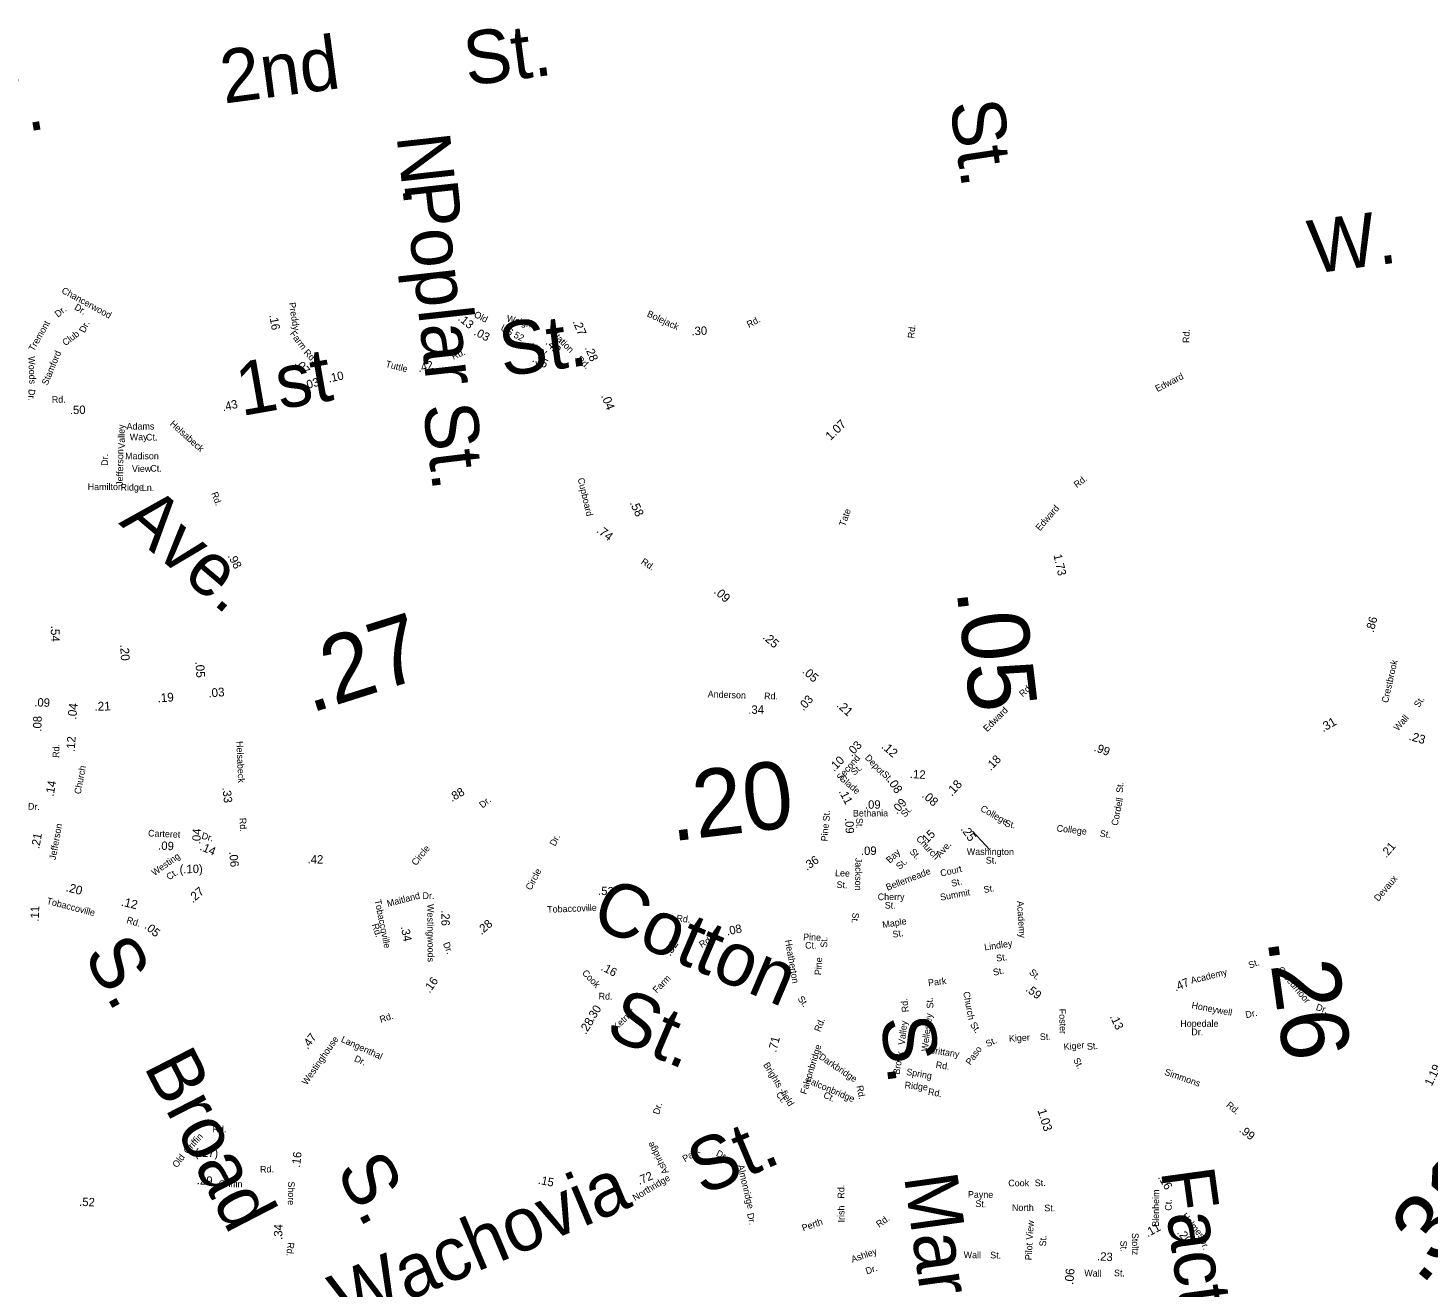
# Model space of a CAD drawing. Extents: x 1553981 to 1780076, y 812965 to 996873.
# Drawn here: x 1630177 to 1632669, y 853916 to 856157 of the extents above; entities that cross this region are included whole.
import ezdxf

# ---------------------------------------------------------------- set-up
doc = ezdxf.new("R2010")
doc.units = 0
for name, color, linetype in [('Exist Road Non-System Type 51 Label', 7, 'Continuous'), ('Exist Road Primary NC Service Mileage Hundredths English Label', 7, 'Continuous'), ('Exist Road Secondary Mileage Hundredths English Label', 7, 'Continuous'), ('Map Preparation Border Antique Large Shape', 7, 'Continuous')]:
    doc.layers.add(name, color=color, linetype=linetype)

msp = doc.modelspace()

# ---------------------------------------------------------------- linework, layer by layer
at = {"layer": 'Exist Road Non-System Type 51 Label'}
msp.add_lwpolyline([(1631858.1, 854727.1), (1631889.3, 854693.9)], dxfattribs=at)

# ---------------------------------------------------------------- texts
for s, height, rotation, p in [('St.', 95, 7.4271, (1630958.8, 856054.2)), ('2nd', 95, 7.5891, (1630525.6, 856022.5)), ('W.', 95, 9.3723, (1630057.1, 855953.2)), ('St.', 95, 278.5556, (1631817.1, 856023.5)), ('N.', 95, 276.3247, (1630832.7, 855965.2)), ('Poplar', 95, 276.3247, (1630846.1, 855881.1)), ('W.', 95, 7.5901, (1632463, 855719.5)), ('Chancerwood', 11.875, 331.4592, (1630235.2, 855686.3)), ('Dr.', 11.88, 37.7398, (1630229.8, 855641.4)), ('Dr.', 11.88, 329.0091, (1630258, 855657.1)), ('Tremont', 11.88, 60.167, (1630187, 855580.6)), ('Dr.', 11.88, 63.6142, (1630277.5, 855613.5)), ('St.', 95, 7.605, (1631022.1, 855536.9)), ('Club', 11.87, 36.9084, (1630243.1, 855590.6)), ('Stamford', 11.88, 67.2967, (1630211.3, 855520.2)), ('1st', 95, 9.919, (1630556.2, 855466.1)), ('Woods', 11.88, 272.3922, (1630177.1, 855572.5)), ('Dr.', 11.88, 268.7345, (1630177.6, 855514.5)), ('St.', 95, 276.9276, (1630879.4, 855485)), ('Valley', 11.88, 91.1337, (1630349.3, 855408.3)), ('Jefferson', 11.88, 89.3274, (1630345.8, 855341.9)), ('Dr.', 11.88, 90, (1630319.1, 855377.7)), ('Madison', 11.87, 359.9238, (1630349.5, 855389.4)), ('View', 11.87, 0.3117, (1630361.7, 855366.7)), ('Ct.', 11.88, 359.3313, (1630394.4, 855367.4)), ('Ave.', 95, 319.6591, (1630336.8, 855275.1)), ('St.', 11.88, 56.7224, (1632653, 854946.3)), ('Wall', 11.88, 49.0847, (1632615.6, 854904.9)), ('Depot', 11.87, 313.0043, (1631665.8, 854857.2)), ('St.', 11.88, 314.4276, (1631695.8, 854827.6)), ('St.', 11.88, 86.7449, (1632125.9, 854795.2)), ('Cordell', 11.87, 78.9341, (1632116.7, 854736.3)), ('St.', 11.88, 88.704, (1631603.8, 854744.7)), ('College', 11.87, 330.4152, (1631871.1, 854764.1)), ('Pine', 11.87, 86.1804, (1631600.3, 854708.8)), ('St.', 11.88, 347.1512, (1631914.6, 854736.2)), ('College', 11.88, 353.4808, (1632007.5, 854726.9)), ('Church', 11.88, 313.1543, (1631756.9, 854713)), ('St.', 11.88, 352.2827, (1632084.2, 854717.7)), ('Bay', 11.88, 44.7999, (1631711.2, 854669.2)), ('St.', 11.88, 313.1543, (1631745.4, 854689.8)), ('Ave.', 11.88, 48.2454, (1631800.4, 854679.5)), ('Washington', 11.88, 359.7339, (1631848, 854685.1)), ('St.', 11.88, 0.2268, (1631881.8, 854669.6)), ('Lee', 11.87, 357.9044, (1631613.3, 854647.2)), ('Jackson', 11.88, 269.2198, (1631649.7, 854679.9)), ('Bellemeade', 11.88, 21.3693, (1631706.7, 854621.1)), ('St.', 11.88, 44.7999, (1631728.9, 854658)), ('Court', 11.88, 12.6952, (1631802.2, 854646.4)), ('Cotton', 95, 336.8873, (1631175.3, 854560.6)), ('St.', 11.87, 357.9044, (1631616, 854626.3)), ('St.', 11.88, 12.6952, (1631821.7, 854628.2)), ('Maitland', 11.88, 14.7534, (1630817.4, 854592.3)), ('Dr.', 11.88, 359.8861, (1630879, 854606.6)), ('Cherry', 11.88, 0.4515, (1631689.5, 854604.4)), ('Summit', 11.88, 10.2169, (1631801.6, 854603.6)), ('St.', 11.87, 9.9072, (1631879.1, 854617.1)), ('St.', 11.88, 263.1054, (1631645, 854583)), ('St.', 11.87, 359.302, (1631701.9, 854589.5)), ('Maple', 11.87, 9.4837, (1631698.8, 854554.6)), ('S.', 95, 298.8589, (1630274.4, 854507.6)), ('Heatherton', 11.87, 279.9144, (1631524.3, 854532.9)), ('Pine', 11.88, 357.9687, (1631556.5, 854533.2)), ('St.', 11.88, 88.704, (1631599.4, 854519.8)), ('St.', 11.87, 9.4837, (1631716.7, 854537.5)), ('Lindley', 11.88, 8.0181, (1631879.9, 854515)), ('Ct.', 11.87, 0.0702, (1631560.2, 854518.1)), ('St.', 11.88, 8.0092, (1631901.2, 854495)), ('Pine', 11.87, 86.1804, (1631588.6, 854470.6)), ('St.', 11.88, 12.7917, (1631896.2, 854469.8)), ('Park', 11.88, 7.0393, (1631779.8, 854451.3)), ('St.', 95, 336.8873, (1631201.4, 854363.4)), ('St.', 11.88, 306.3077, (1631546.3, 854428.7)), ('Church', 11.88, 280.4137, (1631841.5, 854440.8)), ('Rd.', 11.88, 95.6977, (1631744.6, 854405.5)), ('St.', 11.88, 96.0298, (1631789, 854412.4)), ('Foster', 11.88, 272.1215, (1632012.1, 854411)), ('Honeywell', 11.87, 349.1792, (1632247.4, 854412)), ('Dr.', 11.88, 12.4372, (1632345.4, 854394.3)), ('Rd.', 11.87, 68.2472, (1631586.7, 854369)), ('S.', 95, 277.5158, (1631693.9, 854393.4)), ('Valley', 11.88, 83.413, (1631737.4, 854346.1)), ('Wellesley', 11.88, 83.1258, (1631778.5, 854334.7)), ('St.', 11.88, 303.7459, (1631853.3, 854382.6)), ('Hopedale', 11.88, 359.9933, (1632228.1, 854378.9)), ('Langenthal', 11.88, 335.4785, (1630732.9, 854352.7)), ('St.', 11.88, 25.0303, (1631885, 854342.5)), ('Kiger', 11.88, 3.2858, (1631923.4, 854352.2)), ('St.', 11.88, 2.2978, (1631978.3, 854355.2)), ('Dr.', 11.88, 0.3054, (1632247.8, 854363.8)), ('Broad', 95, 297.2142, (1630381.8, 854308.4)), ('Falconbridge', 11.875, 72.81, (1631562.4, 854257.7)), ('Darkbridge', 11.88, 326.0203, (1631583.5, 854323)), ('Brook', 11.88, 80.2186, (1631728.1, 854293.3)), ('Brittany', 11.88, 351.7451, (1631780.6, 854332)), ('Paso', 11.88, 54.5401, (1631854.6, 854309.8)), ('Kiger', 11.88, 6.1203, (1632021, 854337.2)), ('St.', 11.88, 6.1203, (1632062.5, 854337.7)), ('Dr.', 11.88, 335.4785, (1630756.3, 854318.2)), ('Brights -field', 11.875, 301.6463, (1631485.1, 854311.4)), ('Rd.', 11.88, 351.7451, (1631792.1, 854305.9)), ('St.', 11.88, 298.4184, (1632037, 854320)), ('Falconbridge', 11.875, 337.0718, (1631560.7, 854280.1)), ('Spring', 11.88, 350.2233, (1631739.6, 854293.4)), ('Ct.', 11.88, 306.2767, (1631507.5, 854258.4)), ('Ct.', 11.88, 334.7485, (1631591.5, 854253.6)), ('Rd.', 11.88, 281.3645, (1631651.4, 854273.4)), ('Ridge', 11.88, 353.8249, (1631736.9, 854269.8)), ('Rd.', 11.88, 350.0772, (1631778.3, 854258.1)), ('Dr.', 11.88, 74.2178, (1631300.2, 854221.9)), ('St.', 95, 22.8454, (1631377.3, 854078.1)), ('Ashridge', 11.88, 117.3404, (1631317.7, 854120.2)), ('S.', 95, 297.1298, (1630724.1, 854124.4)), ('Wachovia', 95, 22.8454, (1630741.4, 853843.8)), ('Almonridge', 11.88, 283.2611, (1631439.7, 854132.1)), ('Marshall', 95, 277.9213, (1631736.1, 854112.6)), ('Cook', 11.88, 0.5505, (1631921.9, 854094.8)), ('Factory', 95, 277.8122, (1632193.3, 854122.5)), ('Rd.', 11.88, 89.3522, (1631629.9, 854073.1)), ('Payne', 11.88, 359.5513, (1631850, 854074.6)), ('St.', 11.88, 1.0714, (1631969.1, 854095.1)), ('Irish', 11.87, 90.7296, (1631630.4, 854030.8)), ('St.', 11.88, 358.3709, (1631863.2, 854058.2)), ('North', 11.88, 359.8416, (1631928.4, 854051.2)), ('St.', 11.87, 359.3198, (1631986, 854050.6)), ('Dr.', 11.88, 283.2611, (1631456.6, 854046.1)), ('Perth', 11.87, 19.5353, (1631556.8, 854014.7)), ('Rd.', 11.88, 35.5755, (1631691.8, 854021.1)), ('View', 11.88, 85.9709, (1631965.3, 853999.5)), ('Ashley', 11.87, 18.9451, (1631644.4, 853959)), ('Pilot', 11.88, 87.0253, (1631963.5, 853963.1)), ('St.', 11.88, 87.0253, (1631989, 853987.8)), ('Wall', 11.88, 359.684, (1631842.4, 853967.1)), ('St.', 11.88, 358.9513, (1631889.6, 853966.7)), ('Dr.', 11.87, 18.9451, (1631670.1, 853937.9))]:
    msp.add_text(s, height=height, rotation=rotation, dxfattribs=at).set_placement(p)
for s, p in [('Adams', (1630352.1, 855442.3)), ('Way', (1630357.8, 855423.4)), ('Ct.', (1630386.8, 855422.8)), ('Hamilton', (1630282.9, 855334.5)), ('Ridge', (1630341.3, 855333.6)), ('Ln.', (1630379.3, 855333))]:
    msp.add_text(s, height=11.88, dxfattribs=at).set_placement(p)
at = {"layer": 'Exist Road Primary NC Service Mileage Hundredths English Label'}
for s, rotation, p in [('.27', 292.6199, (1631146, 855634.6)), ('.04', 291.7778, (1631196.8, 855502.4)), ('.58', 294.6468, (1631247.5, 855311.8)), ('.09', 318.8745, (1631396.7, 855152.1)), ('.25', 318.8745, (1631483.5, 855071)), ('.05', 318.8745, (1631553.8, 855010.1)), ('.21', 317.9085, (1631615.1, 854950)), ('.31', 29.8003, (1632482.5, 854903.3)), ('.12', 318.3274, (1631694.8, 854876.7)), ('.23', 343.8685, (1632634, 854890.1)), ('.08', 303.9069, (1631705.8, 854816.7)), ('.18', 47.2193, (1631821.2, 854788.6)), ('.08', 319.1979, (1631766.9, 854789.2)), ('.25', 305.1418, (1631836.4, 854731.2)), ('1.03', 287.3387, (1631973.8, 854230.3)), ('.06', 85.1469, (1632037.6, 853919.2))]:
    msp.add_text(s, height=15.62, rotation=rotation, dxfattribs=at).set_placement(p)
at = {"layer": 'Exist Road Secondary Mileage Hundredths English Label'}
for s, height, rotation, p in [('.16', 15, 279.9951, (1630606.1, 855645.9)), ('.13', 15, 320.8792, (1630941, 855638.1)), ('.03', 15, 332.7094, (1630969.1, 855611.5)), ('.30', 15, 2.7224, (1631358.2, 855610)), ('.42', 15, 315.3122, (1631096.9, 855595.7)), ('.28', 15, 292.536, (1631167.7, 855587.8)), ('.07', 15, 311.3959, (1630650.6, 855559.7)), ('.42', 15, 13.5336, (1630872.3, 855544.3)), ('.35', 15, 332.417, (1631073.1, 855563.9)), ('.03', 15, 15.3191, (1630669.4, 855513.2)), ('.10', 15, 12.2641, (1630712.5, 855526)), ('.50', 15, 0.9537, (1630251.3, 855469.7)), ('.43', 15, 13.2965, (1630524.1, 855474.9)), ('1.07', 15.62, 44.3494, (1631605.5, 855422)), ('.74', 15.62, 322.9183, (1631187.5, 855260.5)), ('.98', 15, 298.0586, (1630531.7, 855217.2)), ('1.73', 15, 282.7937, (1632002.3, 855218.9)), ('.05', 120, 276.7369, (1631829.5, 855156.3)), ('.27', 120, 17.5375, (1630678.9, 854937)), ('.86', 15, 74.96, (1632572.1, 855080.1)), ('.54', 15.62, 270.1556, (1630217.3, 855093.2)), ('.20', 15.62, 273.4682, (1630340.6, 855059.3)), ('.05', 15.62, 273.7213, (1630474.6, 855029)), ('.03', 15.62, 4.7201, (1630498.2, 854965.3)), ('.09', 15, 358.0897, (1630187.6, 854949.5)), ('.21', 15.62, 1.1233, (1630295, 854941.7)), ('.19', 15.62, 4.1596, (1630407.7, 854956.4)), ('.03', 15, 48.1457, (1631557.1, 854940.5)), ('.08', 15, 88.4934, (1630200.4, 854904.4)), ('.04', 15.62, 83.1993, (1630262.1, 854925.4)), ('.12', 15, 86.5245, (1630259.8, 854868)), ('.03', 15, 46.1907, (1631643.1, 854859.3)), ('.99', 15, 340.0908, (1632073.3, 854870.4)), ('.10', 15, 46.1494, (1631611.9, 854832.2)), ('.18', 15, 45.38, (1631890.6, 854834.1)), ('.20', 120, 6.9016, (1631323, 854709)), ('.12', 15, 356.5999, (1631746.4, 854821.9)), ('.14', 15, 79.5389, (1630222, 854788.3)), ('.33', 15, 276.4376, (1630522.6, 854804.6)), ('.88', 15, 29.9847, (1630931.3, 854779.1)), ('.11', 15, 297.6042, (1631619.6, 854798.1)), ('.09', 15, 0.1597, (1631666.7, 854767.2)), ('.09', 15, 48.3512, (1631723.7, 854756.6)), ('.04', 15, 86.9838, (1630483.5, 854703.7)), ('.09', 15, 272.5317, (1631631.3, 854750.5)), ('.21', 15, 79.6773, (1630196.6, 854695.1)), ('.09', 15, 357.4069, (1630408.1, 854694.4)), ('.15', 15, 45.7586, (1631773.6, 854701)), ('.21', 15, 49.9174, (1632594.8, 854678.6)), ('.14', 15, 336.5523, (1630481.3, 854694.5)), ('.06', 15, 275.6315, (1630534.6, 854690.5)), ('.42', 15, 359.0907, (1630674.3, 854669.9)), ('.36', 15, 34.6148, (1631563.4, 854656.7)), ('.09', 15, 1.0195, (1631659.7, 854684.7)), ('(.10)', 15, 0.9839, (1630446.6, 854652.2)), ('.20', 15.62, 345.483, (1630243.1, 854620.7)), ('.12', 15.62, 346.4659, (1630341.5, 854594.9)), ('.27', 15.62, 41.1345, (1630469.9, 854598.6)), ('.53', 15, 356.9888, (1631191.2, 854614.1)), ('.11', 15, 88.1325, (1630195.8, 854566.2)), ('.26', 15, 270.4346, (1630912.4, 854586.5)), ('.05', 15, 319.2607, (1630382.8, 854555.8)), ('.28', 15, 40.5545, (1630983.8, 854542)), ('.08', 15, 11.7466, (1631421.4, 854541.6)), ('.34', 15, 281.5141, (1630840.1, 854557)), ('.32', 15, 56.7412, (1631319.9, 854503.7)), ('.26', 120, 277.9891, (1632382.9, 854534.4)), ('.16', 15, 332.3883, (1631195.6, 854480.6)), ('.16', 15, 54.9859, (1630891.8, 854438)), ('.47', 15, 23.0213, (1632219.9, 854441.9)), ('.59', 15, 323.2484, (1631951.6, 854443.7)), ('.30', 15, 58.1349, (1631183.4, 854388)), ('.28', 15.62, 58.1496, (1631169.7, 854364.3)), ('.13', 15, 295.3248, (1632102.4, 854397.2)), ('.47', 15, 52.565, (1630674.5, 854338)), ('.71', 15, 75.7821, (1631508.6, 854332.6)), ('1.19', 15, 64.5341, (1632675.7, 854272.3)), ('.99', 15, 322.5068, (1632331.7, 854193)), ('(.17)', 15, 359.1588, (1630473.8, 854147.4)), ('.16', 15, 83.5987, (1630660.8, 854128)), ('.31', 120, 50.4315, (1632658, 853916.5)), ('.29', 15, 357.852, (1630477, 854098.5)), ('.15', 15, 348.6815, (1631084, 854099.7)), ('.72', 15, 22.2615, (1631264.8, 854097.5)), ('.16', 15, 301.1679, (1632187.8, 854111)), ('.52', 15, 357.7957, (1630267.5, 854060.2)), ('.34', 15, 88.6208, (1630629.2, 853999.6)), ('.11', 15, 28.9038, (1632170.1, 854004)), ('.20', 15, 309.6216, (1632221.5, 854012)), ('.23', 15, 356.7055, (1632079.6, 853963.2))]:
    msp.add_text(s, height=height, rotation=rotation, dxfattribs=at).set_placement(p)
msp.add_text('.34', height=15, dxfattribs=at).set_placement((1631459, 854936.2))
at = {"layer": 'Map Preparation Border Antique Large Shape'}
for s, height, rotation, p in [('Preddy', 11.87, 279.3406, (1630640.8, 855667.7)), ('Bolejack', 11.87, 335.0642, (1631277.5, 855644.3)), ('Old', 11.88, 332.6936, (1630969.5, 855643.5)), ('US 52', 11.88, 331.7522, (1631017, 855619.6)), ('Weight', 11.88, 345.5874, (1631027.8, 855635.1)), ('Rd.', 11.88, 28.0517, (1631460.1, 855623.1)), ('Farm', 11.88, 307.161, (1630642.1, 855612.8)), ('Station', 11.87, 314.4463, (1631106.7, 855613.1)), ('Rd.', 11.88, 84.5497, (1631754.5, 855604.3)), ('Rd.', 11.88, 88.4325, (1632244.2, 855596.3)), ('Rd.', 11.88, 314.1926, (1630666.4, 855578.5)), ('Rd.', 11.88, 23.3282, (1630933.8, 855566.4)), ('Hwy', 11.88, 333.9445, (1631069.5, 855586.9)), ('Tuttle', 11.87, 345.5284, (1630812.4, 855554)), ('Rd.', 11.88, 318.2951, (1631152.4, 855565.8)), ('Edward', 11.87, 27.0714, (1632187.3, 855508.9)), ('Rd.', 11.88, 0.9537, (1630219.1, 855489.7)), ('Helsabeck', 11.88, 318.0911, (1630428.2, 855451.1)), ('Cupboard', 11.87, 283.3108, (1631155.2, 855354.9)), ('Rd.', 11.87, 37.2081, (1632044, 855337.8)), ('Rd.', 11.88, 290.2588, (1630502.7, 855328.8)), ('Edward', 11.87, 48.8877, (1631978.2, 855261)), ('Tate', 11.88, 70.2999, (1631631.2, 855268.9)), ('Rd.', 11.88, 325.8251, (1631267, 855204.5)), ('Crestbrook', 11.88, 77.1061, (1632597.8, 854954.9)), ('Rd.', 11.88, 41.8021, (1631947.6, 854965.3)), ('Anderson', 11.88, 357.8118, (1631386.6, 854965.7)), ('Rd.', 11.88, 359.3705, (1631487.1, 854962.1)), ('Edward', 11.88, 44.8802, (1631884.2, 854903.3)), ('Rd.', 11.88, 88.7138, (1630232.1, 854857.7)), ('Helsabeck', 11.88, 272.5216, (1630547.5, 854887.4)), ('Second', 11.87, 49.2735, (1631623.9, 854816.1)), ('Church', 11.88, 79.5389, (1630270.5, 854792.5)), ('St.', 11.88, 41.3102, (1631647.9, 854825.7)), ('Glade', 11.88, 319.1843, (1631619.9, 854819.8)), ('Dr.', 11.88, 39.698, (1630985.9, 854767.6)), ('Dr.', 11.88, 357.2633, (1630176.3, 854765.8)), ('Bethania', 11.88, 0.2473, (1631645.3, 854753.3)), ('St.', 11.87, 48.3512, (1631738.3, 854751.1)), ('Jefferson', 11.88, 79.6773, (1630225.9, 854675.4)), ('Rd.', 11.87, 273.0136, (1630553.1, 854750.7)), ('St.', 11.88, 271.6699, (1631650.8, 854750.6)), ('Carteret', 11.88, 357.4069, (1630390.2, 854718)), ('Dr.', 11.88, 345.056, (1630484.7, 854714)), ('Dr.', 11.88, 63.0951, (1631115.1, 854699.5)), ('Westing', 11.88, 35.2715, (1630401.7, 854647.1)), ('Circle', 11.88, 50.6797, (1630867.3, 854664.9)), ('Ct.', 11.88, 35.2715, (1630428.1, 854639.4)), ('Circle', 11.88, 61.9976, (1631072.1, 854621)), ('Devaux', 11.87, 49.8064, (1632580.8, 854601.3)), ('Tobaccoville', 11.875, 345.483, (1630208.9, 854598)), ('Tobaccoville', 11.875, 281.5141, (1630793.5, 854604.4)), ('Westingwoods', 11.875, 270.4346, (1630887.4, 854597.5)), ('Tobaccoville', 11.875, 2.2913, (1631101.2, 854581.9)), ('Academy', 11.88, 273.6939, (1631937.2, 854602.9)), ('Rd.', 11.88, 342.8696, (1630351.1, 854564.1)), ('Rd.', 11.88, 287.7796, (1630788.7, 854560.8)), ('Rd.', 11.88, 353.5275, (1631330.6, 854566.8)), ('Rd.', 11.88, 31.4011, (1631375.9, 854519)), ('Dr.', 11.88, 292.6804, (1630915.2, 854527)), ('St.', 11.88, 20.5831, (1632352, 854482.5)), ('Creedmoor', 11.88, 310.1051, (1632400.5, 854480.2)), ('Cook', 11.88, 313.6186, (1631162.2, 854474)), ('Farm', 11.88, 45.4357, (1631296, 854437.9)), ('St.', 11.88, 319.5527, (1631958.1, 854474.2)), ('Academy', 11.87, 13.8956, (1632248.3, 854455.6)), ('Rd.', 11.88, 358.3672, (1631192.4, 854427.8)), ('Ketner', 11.88, 44.1665, (1631224.7, 854372)), ('Dr.', 11.88, 341.1042, (1632468.6, 854409.3)), ('Rd.', 11.88, 18.0278, (1630804.8, 854386)), ('Westinghouse', 11.875, 55.2647, (1630672.9, 854274.4)), ('Simmons', 11.88, 340.6391, (1632198.9, 854293.9)), ('Rd.', 11.88, 320.6935, (1632308.8, 854237.7)), ('Griffin', 11.88, 48.1944, (1630460.9, 854151.6)), ('Rd.', 11.88, 359.6328, (1630505, 854191.2)), ('Park', 11.88, 31.0484, (1631346.2, 854137.7)), ('Dr.', 11.87, 333.1158, (1631400.5, 854149.8)), ('Old', 11.88, 52.1316, (1630441.7, 854127)), ('Rd.', 11.88, 1.6677, (1630589.9, 854119.2)), ('Northridge', 11.88, 31.0759, (1631257.4, 854068.5)), ('Griffin', 11.87, 358.7104, (1630516, 854094)), ('Shore', 11.87, 269.1687, (1630639.8, 854103.8)), ('Blenheim', 11.88, 89.3428, (1632189.9, 854023)), ('Ct.', 11.88, 89.3428, (1632212.8, 854051.5)), ('Holmes', 11.88, 309.6216, (1632229.8, 854041.8)), ('Stoltz', 11.88, 271.1444, (1632141.8, 854012)), ('Rd.', 11.87, 264.4286, (1630639, 853995.6)), ('St.', 11.88, 271.1444, (1632121.4, 853998.1)), ('Dr.', 11.88, 295.7488, (1632261, 853999.8)), ('Wall', 11.88, 358.2844, (1632057, 853934.9)), ('St.', 11.87, 357.5467, (1632109.9, 853935.1))]:
    msp.add_text(s, height=height, rotation=rotation, dxfattribs=at).set_placement(p)

doc.saveas('drawing.dxf')
